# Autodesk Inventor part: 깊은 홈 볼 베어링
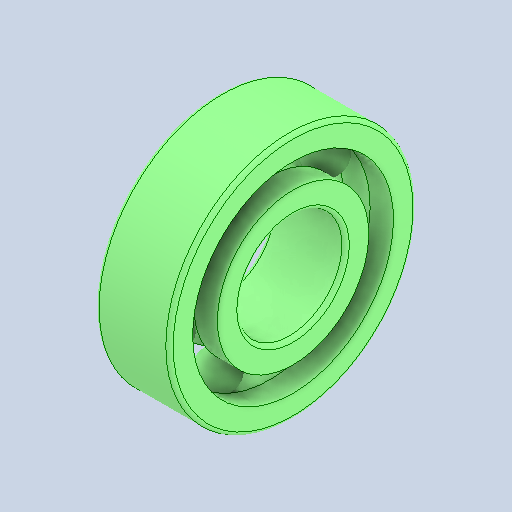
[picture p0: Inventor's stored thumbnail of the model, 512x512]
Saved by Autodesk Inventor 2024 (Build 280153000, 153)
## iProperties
Created: 2026-07
Part Number: 깊은 홈 볼 베어링
Material: 강철, 연강
Description: 깊은 그루브 볼 베어링
Document SubType Name: Modeling
Designer: com
Density: 7.86 g/cm^3
Appearance: 기본값
Author: jhkim
Revision Number: 1
Sending System: Autodesk Inventor 2027
Preprocessor: ST-DEVELOPER v20.1
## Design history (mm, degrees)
node "깊은 홈 볼 베어링 62031"
node "솔리드1"
node "솔리드2"
node "솔리드3"
node "솔리드4"
node "솔리드5"
node "솔리드6"
node "솔리드7"
node "솔리드8"
node "솔리드9"
body "Solid1"
node "Solid1:1"
node "Solid1:2"
node "Solid1:3"
node "Solid1:4"
node "Solid1:5"
node "Solid1:6"
node "Solid1:7"
node "Solid1:8"
